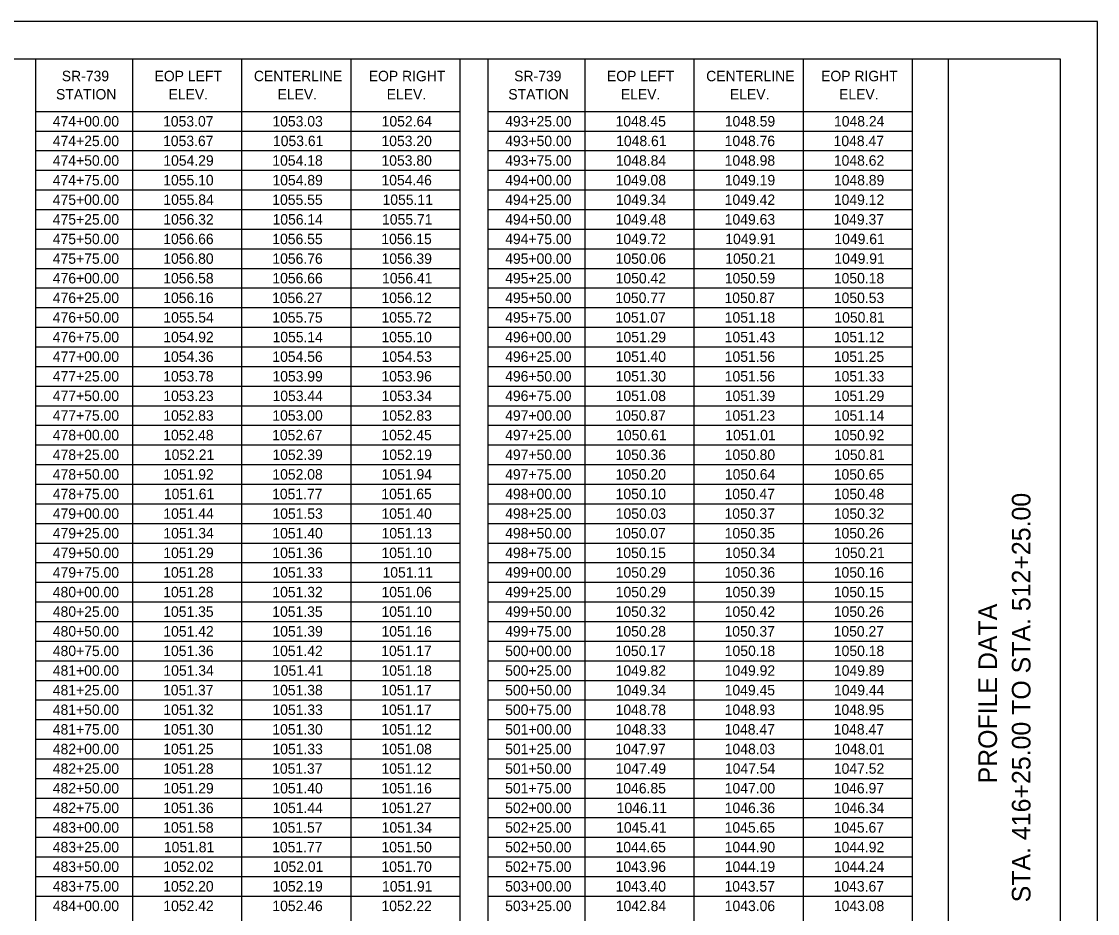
# Model space of a CAD drawing. Extents: x 0 to 34, y 0 to 22.
# Drawn here: x 19.54 to 34, y 10.02 to 22 of the extents above; entities that cross this region are included whole.
import ezdxf

# ---------------------------------------------------------------- set-up
doc = ezdxf.new("R2010")
doc.units = 0
for name, color, linetype in [('SH_Border', 7, 'Continuous'), ('SH_Cut_Line', 7, 'Continuous'), ('SH_Data', 7, 'Continuous'), ('SH_Text', 7, 'Continuous')]:
    doc.layers.add(name, color=color, linetype=linetype)

msp = doc.modelspace()

# ---------------------------------------------------------------- linework, layer by layer
at = {"layer": 'SH_Border'}
msp.add_line((32, 0.5), (32, 21.5), dxfattribs=at)
msp.add_lwpolyline([(1.5, 21.5), (33.5, 21.5), (33.5, 0.5), (1.5, 0.5)], close=True, dxfattribs=at)
at = {"layer": 'SH_Cut_Line'}
msp.add_lwpolyline([(0, 0), (34, 0), (34, 22), (0, 22)], close=True, dxfattribs=at)
at = {"layer": 'SH_Text'}
for p, q in [((19.733, 21.5), (25.432, 21.5)), ((19.733, 21.5), (19.733, 0.5)), ((21.034, 21.5), (21.034, 0.5)), ((22.5, 21.5), (22.5, 0.5)), ((23.966, 21.5), (23.966, 0.5)), ((25.432, 21.5), (25.432, 0.5)), ((25.811, 21.5), (31.509, 21.5)), ((25.811, 21.5), (25.811, 0.5)), ((27.112, 21.5), (27.112, 0.5)), ((28.578, 21.5), (28.578, 0.5)), ((30.044, 21.5), (30.044, 0.5)), ((31.509, 21.5), (31.509, 0.5)), ((19.733, 20.792), (25.432, 20.792)), ((25.811, 20.792), (31.509, 20.792)), ((19.733, 20.528), (25.432, 20.528)), ((25.811, 20.528), (31.509, 20.528)), ((19.733, 20.265), (25.432, 20.265)), ((25.811, 20.265), (31.509, 20.265)), ((19.733, 20.001), (25.432, 20.001)), ((25.811, 20.001), (31.509, 20.001)), ((19.733, 19.738), (25.432, 19.738)), ((25.811, 19.738), (31.509, 19.738)), ((19.733, 19.474), (25.432, 19.474)), ((25.811, 19.474), (31.509, 19.474)), ((19.733, 19.211), (25.432, 19.211)), ((25.811, 19.211), (31.509, 19.211)), ((19.733, 18.947), (25.432, 18.947)), ((25.811, 18.947), (31.509, 18.947)), ((19.733, 18.684), (25.432, 18.684)), ((25.811, 18.684), (31.509, 18.684)), ((19.733, 18.42), (25.432, 18.42)), ((25.811, 18.42), (31.509, 18.42)), ((19.733, 18.156), (25.432, 18.156)), ((25.811, 18.156), (31.509, 18.156)), ((19.733, 17.893), (25.432, 17.893)), ((25.811, 17.893), (31.509, 17.893)), ((19.733, 17.629), (25.432, 17.629)), ((25.811, 17.629), (31.509, 17.629)), ((19.733, 17.366), (25.432, 17.366)), ((25.811, 17.366), (31.509, 17.366)), ((19.733, 17.102), (25.432, 17.102)), ((25.811, 17.102), (31.509, 17.102)), ((19.733, 16.839), (25.432, 16.839)), ((25.811, 16.839), (31.509, 16.839)), ((19.733, 16.575), (25.432, 16.575)), ((25.811, 16.575), (31.509, 16.575)), ((19.733, 16.312), (25.432, 16.312)), ((25.811, 16.312), (31.509, 16.312)), ((19.733, 16.048), (25.432, 16.048)), ((25.811, 16.048), (31.509, 16.048)), ((19.733, 15.785), (25.432, 15.785)), ((25.811, 15.785), (31.509, 15.785)), ((19.733, 15.521), (25.432, 15.521)), ((25.811, 15.521), (31.509, 15.521)), ((19.733, 15.258), (25.432, 15.258)), ((25.811, 15.258), (31.509, 15.258)), ((19.733, 14.994), (25.432, 14.994)), ((25.811, 14.994), (31.509, 14.994)), ((19.733, 14.731), (25.432, 14.731)), ((25.811, 14.731), (31.509, 14.731)), ((19.733, 14.467), (25.432, 14.467)), ((25.811, 14.467), (31.509, 14.467)), ((19.733, 14.204), (25.432, 14.204)), ((25.811, 14.204), (31.509, 14.204)), ((19.733, 13.94), (25.432, 13.94)), ((25.811, 13.94), (31.509, 13.94)), ((19.733, 13.676), (25.432, 13.676)), ((25.811, 13.676), (31.509, 13.676)), ((19.733, 13.413), (25.432, 13.413)), ((25.811, 13.413), (31.509, 13.413)), ((19.733, 13.149), (25.432, 13.149)), ((25.811, 13.149), (31.509, 13.149)), ((19.733, 12.886), (25.432, 12.886)), ((25.811, 12.886), (31.509, 12.886)), ((19.733, 12.622), (25.432, 12.622)), ((25.811, 12.622), (31.509, 12.622)), ((19.733, 12.359), (25.432, 12.359)), ((25.811, 12.359), (31.509, 12.359)), ((19.733, 12.095), (25.432, 12.095)), ((25.811, 12.095), (31.509, 12.095)), ((19.733, 11.832), (25.432, 11.832)), ((25.811, 11.832), (31.509, 11.832)), ((19.733, 11.568), (25.432, 11.568)), ((25.811, 11.568), (31.509, 11.568)), ((19.733, 11.305), (25.432, 11.305)), ((25.811, 11.305), (31.509, 11.305)), ((19.733, 11.041), (25.432, 11.041)), ((25.811, 11.041), (31.509, 11.041)), ((19.733, 10.778), (25.432, 10.778)), ((25.811, 10.778), (31.509, 10.778)), ((19.733, 10.514), (25.432, 10.514)), ((25.811, 10.514), (31.509, 10.514)), ((19.733, 10.251), (25.432, 10.251)), ((25.811, 10.251), (31.509, 10.251))]:
    msp.add_line(p, q, dxfattribs=at)

# ---------------------------------------------------------------- texts
at = {"layer": 'SH_Data'}
for s, p in [('STA. 416+25.00 TO STA. 512+25.00', (33.1, 10.167)), ('PROFILE DATA', (32.65, 11.764))]:
    msp.add_text(s, height=0.25, rotation=90, dxfattribs=at).set_placement(p)
at = {"layer": 'SH_Text'}
for s, p in [('SR-739 ', (20.085, 21.198)), ('EOP LEFT ', (21.331, 21.198)), ('CENTERLINE ', (22.666, 21.198)), ('EOP RIGHT ', (24.209, 21.198)), ('SR-739 ', (26.163, 21.198)), ('EOP LEFT ', (27.409, 21.198)), ('CENTERLINE ', (28.743, 21.198)), ('EOP RIGHT ', (30.287, 21.198)), ('STATION', (20.007, 20.953)), ('ELEV.', (21.519, 20.953)), ('ELEV.', (22.984, 20.953)), ('ELEV.', (24.45, 20.953)), ('STATION', (26.084, 20.953)), ('ELEV.', (27.596, 20.953)), ('ELEV.', (29.062, 20.953)), ('ELEV.', (30.528, 20.953)), ('474+00.00', (19.964, 20.59)), ('1053.07', (21.446, 20.59)), ('1053.03', (22.915, 20.59)), ('1052.64', (24.382, 20.59)), ('493+25.00', (26.042, 20.59)), ('1048.45', (27.525, 20.59)), ('1048.59', (28.993, 20.59)), ('1048.24', (30.46, 20.59)), ('474+25.00', (19.964, 20.326)), ('1053.67', (21.446, 20.326)), ('1053.61', (22.922, 20.326)), ('1053.20', (24.38, 20.326)), ('493+50.00', (26.042, 20.326)), ('1048.61', (27.533, 20.326)), ('1048.76', (28.992, 20.326)), ('1048.47', (30.455, 20.326)), ('474+50.00', (19.964, 20.063)), ('1054.29', (21.449, 20.063)), ('1054.18', (22.914, 20.063)), ('1053.80', (24.38, 20.063)), ('493+75.00', (26.042, 20.063)), ('1048.84', (27.528, 20.063)), ('1048.98', (28.992, 20.063)), ('1048.62', (30.458, 20.063)), ('474+75.00', (19.964, 19.799)), ('1055.10', (21.448, 19.799)), ('1054.89', (22.915, 19.799)), ('1054.46', (24.38, 19.799)), ('494+00.00', (26.042, 19.799)), ('1049.08', (27.526, 19.799)), ('1049.19', (28.993, 19.799)), ('1048.89', (30.459, 19.799)), ('475+00.00', (19.964, 19.536)), ('1055.84', (21.45, 19.536)), ('1055.55', (22.913, 19.536)), ('1055.11', (24.394, 19.536)), ('494+25.00', (26.042, 19.536)), ('1049.34', (27.528, 19.536)), ('1049.42', (28.992, 19.536)), ('1049.12', (30.458, 19.536)), ('475+25.00', (19.964, 19.272)), ('1056.32', (21.449, 19.272)), ('1056.14', (22.916, 19.272)), ('1055.71', (24.388, 19.272)), ('494+50.00', (26.042, 19.272)), ('1049.48', (27.526, 19.272)), ('1049.63', (28.992, 19.272)), ('1049.37', (30.455, 19.272)), ('475+50.00', (19.964, 19.009)), ('1056.66', (21.448, 19.009)), ('1056.55', (22.913, 19.009)), ('1056.15', (24.379, 19.009)), ('494+75.00', (26.042, 19.009)), ('1049.72', (27.526, 19.009)), ('1049.91', (28.999, 19.009)), ('1049.61', (30.465, 19.009)), ('475+75.00', (19.964, 18.745)), ('1056.80', (21.448, 18.745)), ('1056.76', (22.914, 18.745)), ('1056.39', (24.381, 18.745)), ('495+00.00', (26.042, 18.745)), ('1050.06', (27.526, 18.745)), ('1050.21', (28.999, 18.745)), ('1049.91', (30.465, 18.745)), ('476+00.00', (19.964, 18.482)), ('1056.58', (21.448, 18.482)), ('1056.66', (22.914, 18.482)), ('1056.41', (24.388, 18.482)), ('495+25.00', (26.042, 18.482)), ('1050.42', (27.526, 18.482)), ('1050.59', (28.993, 18.482)), ('1050.18', (30.458, 18.482)), ('476+25.00', (19.964, 18.218)), ('1056.16', (21.448, 18.218)), ('1056.27', (22.911, 18.218)), ('1056.12', (24.38, 18.218)), ('495+50.00', (26.042, 18.218)), ('1050.77', (27.523, 18.218)), ('1050.87', (28.989, 18.218)), ('1050.53', (30.458, 18.218)), ('476+50.00', (19.964, 17.955)), ('1055.54', (21.45, 17.955)), ('1055.75', (22.913, 17.955)), ('1055.72', (24.38, 17.955)), ('495+75.00', (26.042, 17.955)), ('1051.07', (27.523, 17.955)), ('1051.18', (28.992, 17.955)), ('1050.81', (30.465, 17.955)), ('476+75.00', (19.964, 17.691)), ('1054.92', (21.449, 17.691)), ('1055.14', (22.916, 17.691)), ('1055.10', (24.38, 17.691)), ('496+00.00', (26.042, 17.691)), ('1051.29', (27.527, 17.691)), ('1051.43', (28.992, 17.691)), ('1051.12', (30.458, 17.691)), ('477+00.00', (19.964, 17.428)), ('1054.36', (21.448, 17.428)), ('1054.56', (22.914, 17.428)), ('1054.53', (24.381, 17.428)), ('496+25.00', (26.042, 17.428)), ('1051.40', (27.526, 17.428)), ('1051.56', (28.992, 17.428)), ('1051.25', (30.457, 17.428)), ('477+25.00', (19.964, 17.164)), ('1053.78', (21.448, 17.164)), ('1053.99', (22.915, 17.164)), ('1053.96', (24.38, 17.164)), ('496+50.00', (26.042, 17.164)), ('1051.30', (27.526, 17.164)), ('1051.56', (28.992, 17.164)), ('1051.33', (30.458, 17.164)), ('477+50.00', (19.964, 16.901)), ('1053.23', (21.449, 16.901)), ('1053.44', (22.916, 16.901)), ('1053.34', (24.382, 16.901)), ('496+75.00', (26.042, 16.901)), ('1051.08', (27.526, 16.901)), ('1051.39', (28.993, 16.901)), ('1051.29', (30.459, 16.901)), ('477+75.00', (19.964, 16.637)), ('1052.83', (21.449, 16.637)), ('1053.00', (22.914, 16.637)), ('1052.83', (24.381, 16.637)), ('497+00.00', (26.042, 16.637)), ('1050.87', (27.523, 16.637)), ('1051.23', (28.992, 16.637)), ('1051.14', (30.46, 16.637)), ('478+00.00', (19.964, 16.374)), ('1052.48', (21.448, 16.374)), ('1052.67', (22.911, 16.374)), ('1052.45', (24.379, 16.374)), ('497+25.00', (26.042, 16.374)), ('1050.61', (27.533, 16.374)), ('1051.01', (28.999, 16.374)), ('1050.92', (30.458, 16.374)), ('478+25.00', (19.964, 16.11)), ('1052.21', (21.456, 16.11)), ('1052.39', (22.915, 16.11)), ('1052.19', (24.381, 16.11)), ('497+50.00', (26.042, 16.11)), ('1050.36', (27.526, 16.11)), ('1050.80', (28.992, 16.11)), ('1050.81', (30.465, 16.11)), ('478+50.00', (19.964, 15.846)), ('1051.92', (21.449, 15.846)), ('1052.08', (22.914, 15.846)), ('1051.94', (24.382, 15.846)), ('497+75.00', (26.042, 15.846)), ('1050.20', (27.526, 15.846)), ('1050.64', (28.994, 15.846)), ('1050.65', (30.457, 15.846)), ('478+75.00', (19.964, 15.583)), ('1051.61', (21.456, 15.583)), ('1051.77', (22.911, 15.583)), ('1051.65', (24.379, 15.583)), ('498+00.00', (26.042, 15.583)), ('1050.10', (27.526, 15.583)), ('1050.47', (28.989, 15.583)), ('1050.48', (30.458, 15.583)), ('479+00.00', (19.964, 15.319)), ('1051.44', (21.45, 15.319)), ('1051.53', (22.915, 15.319)), ('1051.40', (24.38, 15.319)), ('498+25.00', (26.042, 15.319)), ('1050.03', (27.527, 15.319)), ('1050.37', (28.989, 15.319)), ('1050.32', (30.458, 15.319)), ('479+25.00', (19.964, 15.056)), ('1051.34', (21.45, 15.056)), ('1051.40', (22.914, 15.056)), ('1051.13', (24.381, 15.056)), ('498+50.00', (26.042, 15.056)), ('1050.07', (27.523, 15.056)), ('1050.35', (28.991, 15.056)), ('1050.26', (30.457, 15.056)), ('479+50.00', (19.964, 14.792)), ('1051.29', (21.449, 14.792)), ('1051.36', (22.914, 14.792)), ('1051.10', (24.38, 14.792)), ('498+75.00', (26.042, 14.792)), ('1050.15', (27.525, 14.792)), ('1050.34', (28.994, 14.792)), ('1050.21', (30.465, 14.792)), ('479+75.00', (19.964, 14.529)), ('1051.28', (21.448, 14.529)), ('1051.33', (22.915, 14.529)), ('1051.11', (24.394, 14.529)), ('499+00.00', (26.042, 14.529)), ('1050.29', (27.527, 14.529)), ('1050.36', (28.992, 14.529)), ('1050.16', (30.457, 14.529)), ('480+00.00', (19.964, 14.265)), ('1051.28', (21.448, 14.265)), ('1051.32', (22.914, 14.265)), ('1051.06', (24.38, 14.265)), ('499+25.00', (26.042, 14.265)), ('1050.29', (27.527, 14.265)), ('1050.39', (28.993, 14.265)), ('1050.15', (30.457, 14.265)), ('480+25.00', (19.964, 14.002)), ('1051.35', (21.448, 14.002)), ('1051.35', (22.913, 14.002)), ('1051.10', (24.38, 14.002)), ('499+50.00', (26.042, 14.002)), ('1050.32', (27.526, 14.002)), ('1050.42', (28.992, 14.002)), ('1050.26', (30.457, 14.002)), ('480+50.00', (19.964, 13.738)), ('1051.42', (21.449, 13.738)), ('1051.39', (22.915, 13.738)), ('1051.16', (24.38, 13.738)), ('499+75.00', (26.042, 13.738)), ('1050.28', (27.526, 13.738)), ('1050.37', (28.989, 13.738)), ('1050.27', (30.455, 13.738)), ('480+75.00', (19.964, 13.475)), ('1051.36', (21.448, 13.475)), ('1051.42', (22.914, 13.475)), ('1051.17', (24.377, 13.475)), ('500+00.00', (26.042, 13.475)), ('1050.17', (27.523, 13.475)), ('1050.18', (28.992, 13.475)), ('1050.18', (30.458, 13.475)), ('481+00.00', (19.964, 13.211)), ('1051.34', (21.45, 13.211)), ('1051.41', (22.922, 13.211)), ('1051.18', (24.38, 13.211)), ('500+25.00', (26.042, 13.211)), ('1049.82', (27.526, 13.211)), ('1049.92', (28.992, 13.211)), ('1049.89', (30.459, 13.211)), ('481+25.00', (19.964, 12.948)), ('1051.37', (21.446, 12.948)), ('1051.38', (22.914, 12.948)), ('1051.17', (24.377, 12.948)), ('500+50.00', (26.042, 12.948)), ('1049.34', (27.528, 12.948)), ('1049.45', (28.991, 12.948)), ('1049.44', (30.46, 12.948)), ('481+50.00', (19.964, 12.684)), ('1051.32', (21.449, 12.684)), ('1051.33', (22.915, 12.684)), ('1051.17', (24.377, 12.684)), ('500+75.00', (26.042, 12.684)), ('1048.78', (27.526, 12.684)), ('1048.93', (28.992, 12.684)), ('1048.95', (30.457, 12.684)), ('481+75.00', (19.964, 12.421)), ('1051.30', (21.448, 12.421)), ('1051.30', (22.914, 12.421)), ('1051.12', (24.38, 12.421)), ('501+00.00', (26.042, 12.421)), ('1048.33', (27.527, 12.421)), ('1048.47', (28.989, 12.421)), ('1048.47', (30.455, 12.421)), ('482+00.00', (19.964, 12.157)), ('1051.25', (21.448, 12.157)), ('1051.33', (22.915, 12.157)), ('1051.08', (24.38, 12.157)), ('501+25.00', (26.042, 12.157)), ('1047.97', (27.523, 12.157)), ('1048.03', (28.992, 12.157)), ('1048.01', (30.465, 12.157)), ('482+25.00', (19.964, 11.894)), ('1051.28', (21.448, 11.894)), ('1051.37', (22.911, 11.894)), ('1051.12', (24.38, 11.894)), ('501+50.00', (26.042, 11.894)), ('1047.49', (27.527, 11.894)), ('1047.54', (28.994, 11.894)), ('1047.52', (30.458, 11.894)), ('482+50.00', (19.964, 11.63)), ('1051.29', (21.449, 11.63)), ('1051.40', (22.914, 11.63)), ('1051.16', (24.38, 11.63)), ('501+75.00', (26.042, 11.63)), ('1046.85', (27.525, 11.63)), ('1047.00', (28.992, 11.63)), ('1046.97', (30.455, 11.63)), ('482+75.00', (19.964, 11.366)), ('1051.36', (21.448, 11.366)), ('1051.44', (22.916, 11.366)), ('1051.27', (24.377, 11.366)), ('502+00.00', (26.042, 11.366)), ('1046.11', (27.54, 11.366)), ('1046.36', (28.992, 11.366)), ('1046.34', (30.46, 11.366)), ('483+00.00', (19.964, 11.103)), ('1051.58', (21.448, 11.103)), ('1051.57', (22.911, 11.103)), ('1051.34', (24.382, 11.103)), ('502+25.00', (26.042, 11.103)), ('1045.41', (27.533, 11.103)), ('1045.65', (28.991, 11.103)), ('1045.67', (30.455, 11.103)), ('483+25.00', (19.964, 10.839)), ('1051.81', (21.456, 10.839)), ('1051.77', (22.911, 10.839)), ('1051.50', (24.38, 10.839)), ('502+50.00', (26.042, 10.839)), ('1044.65', (27.525, 10.839)), ('1044.90', (28.992, 10.839)), ('1044.92', (30.458, 10.839)), ('483+50.00', (19.964, 10.576)), ('1052.02', (21.449, 10.576)), ('1052.01', (22.922, 10.576)), ('1051.70', (24.38, 10.576)), ('502+75.00', (26.042, 10.576)), ('1043.96', (27.526, 10.576)), ('1044.19', (28.993, 10.576)), ('1044.24', (30.46, 10.576)), ('483+75.00', (19.964, 10.312)), ('1052.20', (21.448, 10.312)), ('1052.19', (22.915, 10.312)), ('1051.91', (24.388, 10.312)), ('503+00.00', (26.042, 10.312)), ('1043.40', (27.526, 10.312)), ('1043.57', (28.989, 10.312)), ('1043.67', (30.455, 10.312)), ('484+00.00', (19.964, 10.049)), ('1052.42', (21.449, 10.049)), ('1052.46', (22.914, 10.049)), ('1052.22', (24.38, 10.049)), ('503+25.00', (26.042, 10.049)), ('1042.84', (27.528, 10.049)), ('1043.06', (28.992, 10.049)), ('1043.08', (30.458, 10.049))]:
    msp.add_text(s, height=0.14, dxfattribs=at).set_placement(p)

doc.saveas('drawing.dxf')
